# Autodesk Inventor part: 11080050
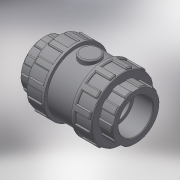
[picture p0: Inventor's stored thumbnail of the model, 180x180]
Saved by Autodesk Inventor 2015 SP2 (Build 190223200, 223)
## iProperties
Created: 2017-11
Part Number: 11080050
Material: Generic
Description: PLASSON CHECK VALVE CEM 50 PTFE COATED SPRING + EPDM O-RING
Document SubType Name: Modeling
Designer: KIM
Density: 1 g/cm^3
Appearance: Default
Author: KIM
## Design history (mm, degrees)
derived "110800 - 110600 110900-110000.ipt"
feature "Solid1::110800 - 110600 110900-110000.ipt"
tag "TaggingFeature1"
body "Solid1"
other parameters: "d0" = 142, "d2" = 96, "d3" = 31, "d5" = 21.7, "d8" = 86.4, "d13" = 1.5, "d23" = 31, "d24" = 92.16, "d25" = 1, "d26" = 1.5, "d27" = 14.4, "d28" = 7.2, "d29" = 23.25, "d30" = 0, "d35" = 1.5, "d39" = 48, "d45" = 360 deg, "d47" = 1, "d50" = 48, "d51" = 28.8, "d53" = 0, "d54" = 1.92, "d56" = 5, "d57" = 21.7, "d58" = 0, "d59" = 1.5, "d61" = 360 deg, "l_" = 31, "H_" = 142, "K_" = 96
